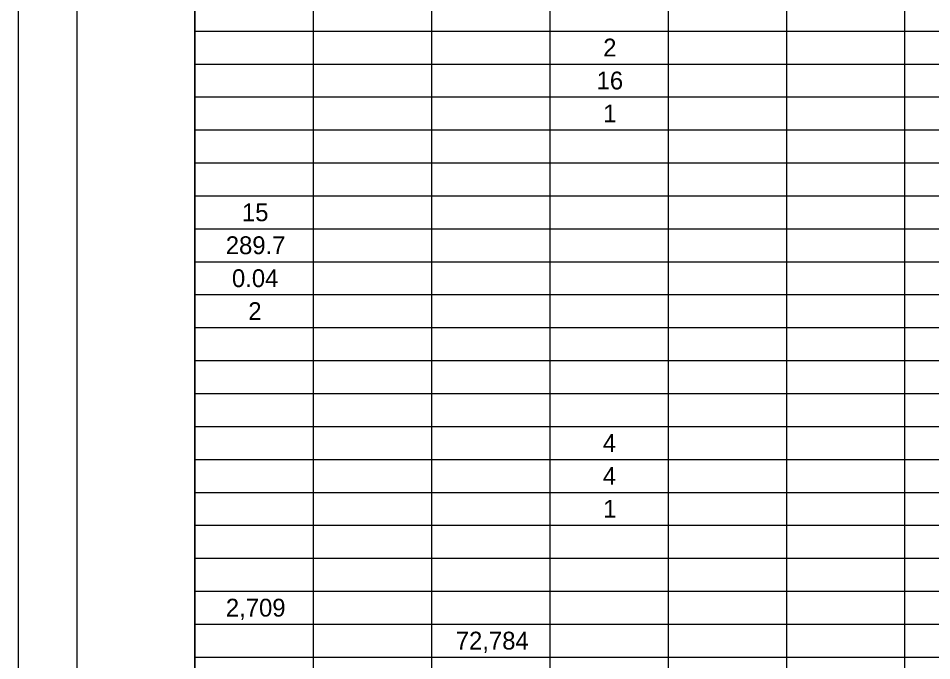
# Model space of a CAD drawing. Extents: x 0 to 34, y 0 to 22.
# Drawn here: x 0 to 7.76, y 11.11 to 16.57 of the extents above; entities that cross this region are included whole.
import ezdxf

# ---------------------------------------------------------------- set-up
doc = ezdxf.new("R2010")
doc.units = 0
for name, color, linetype in [('Default', 7, 'Continuous'), ('SH_Border', 7, 'Continuous'), ('SH_Cut_Line', 7, 'Continuous')]:
    doc.layers.add(name, color=color, linetype=linetype)

msp = doc.modelspace()

# ---------------------------------------------------------------- linework, layer by layer
at = {"layer": 'Default'}
for p, q in [((1.5, 21.5), (1.5, 0.5)), ((2.5047, 20.94), (2.5047, 0.5)), ((3.5094, 20.94), (3.5094, 0.5)), ((4.5141, 20.94), (4.5141, 0.5)), ((5.5188, 20.94), (5.5188, 0.5)), ((6.5235, 20.94), (6.5235, 0.5)), ((7.5282, 20.94), (7.5282, 0.5)), ((1.5, 16.46), (32.0035, 16.46)), ((1.5, 16.18), (32.0035, 16.18)), ((1.5, 15.9), (32.0035, 15.9)), ((1.5, 15.62), (32.0035, 15.62)), ((1.5, 15.34), (32.0035, 15.34)), ((1.5, 15.06), (32.0035, 15.06)), ((1.5, 14.78), (32.0035, 14.78)), ((1.5, 14.5), (32.0035, 14.5)), ((1.5, 14.22), (32.0035, 14.22)), ((1.5, 13.94), (32.0035, 13.94)), ((1.5, 13.66), (32.0035, 13.66)), ((1.5, 13.38), (32.0035, 13.38)), ((1.5, 13.1), (32.0035, 13.1)), ((1.5, 12.82), (32.0035, 12.82)), ((1.5, 12.54), (32.0035, 12.54)), ((1.5, 12.26), (32.0035, 12.26)), ((1.5, 11.98), (32.0035, 11.98)), ((1.5, 11.7), (32.0035, 11.7)), ((1.5, 11.42), (32.0035, 11.42)), ((1.5, 11.14), (32.0035, 11.14))]:
    msp.add_line(p, q, dxfattribs=at)
at = {"layer": 'SH_Border'}
for points in [[(0.5, 21.5), (1.5, 21.5), (1.5, 0.5), (0.5, 0.5)], [(1.5, 21.5), (33.5, 21.5), (33.5, 0.5), (1.5, 0.5)]]:
    msp.add_lwpolyline(points, close=True, dxfattribs=at)
at = {"layer": 'SH_Cut_Line'}
msp.add_lwpolyline([(0, 0), (34, 0), (34, 22), (0, 22)], close=True, dxfattribs=at)

# ---------------------------------------------------------------- texts
at = {"layer": 'Default'}
for s, height, p in [('2', 0.1515, (4.968, 16.2442)), ('16', 0.15153, (4.9119, 15.9642)), ('1', 0.1515, (4.9679, 15.6842)), ('15', 0.15153, (1.8998, 14.8442)), ('289.7', 0.15153, (1.7624, 14.5642)), ('0.04', 0.15153, (1.815, 14.2842)), ('2', 0.1515, (1.9539, 14.0042)), ('4', 0.1515, (4.9651, 12.8842)), ('4', 0.1515, (4.9651, 12.6042)), ('1', 0.1515, (4.9679, 12.3242)), ('2,709', 0.15153, (1.7633, 11.4842)), ('72,784', 0.15153, (3.7159, 11.2042))]:
    msp.add_text(s, height=height, dxfattribs=at).set_placement(p)

doc.saveas('drawing.dxf')
